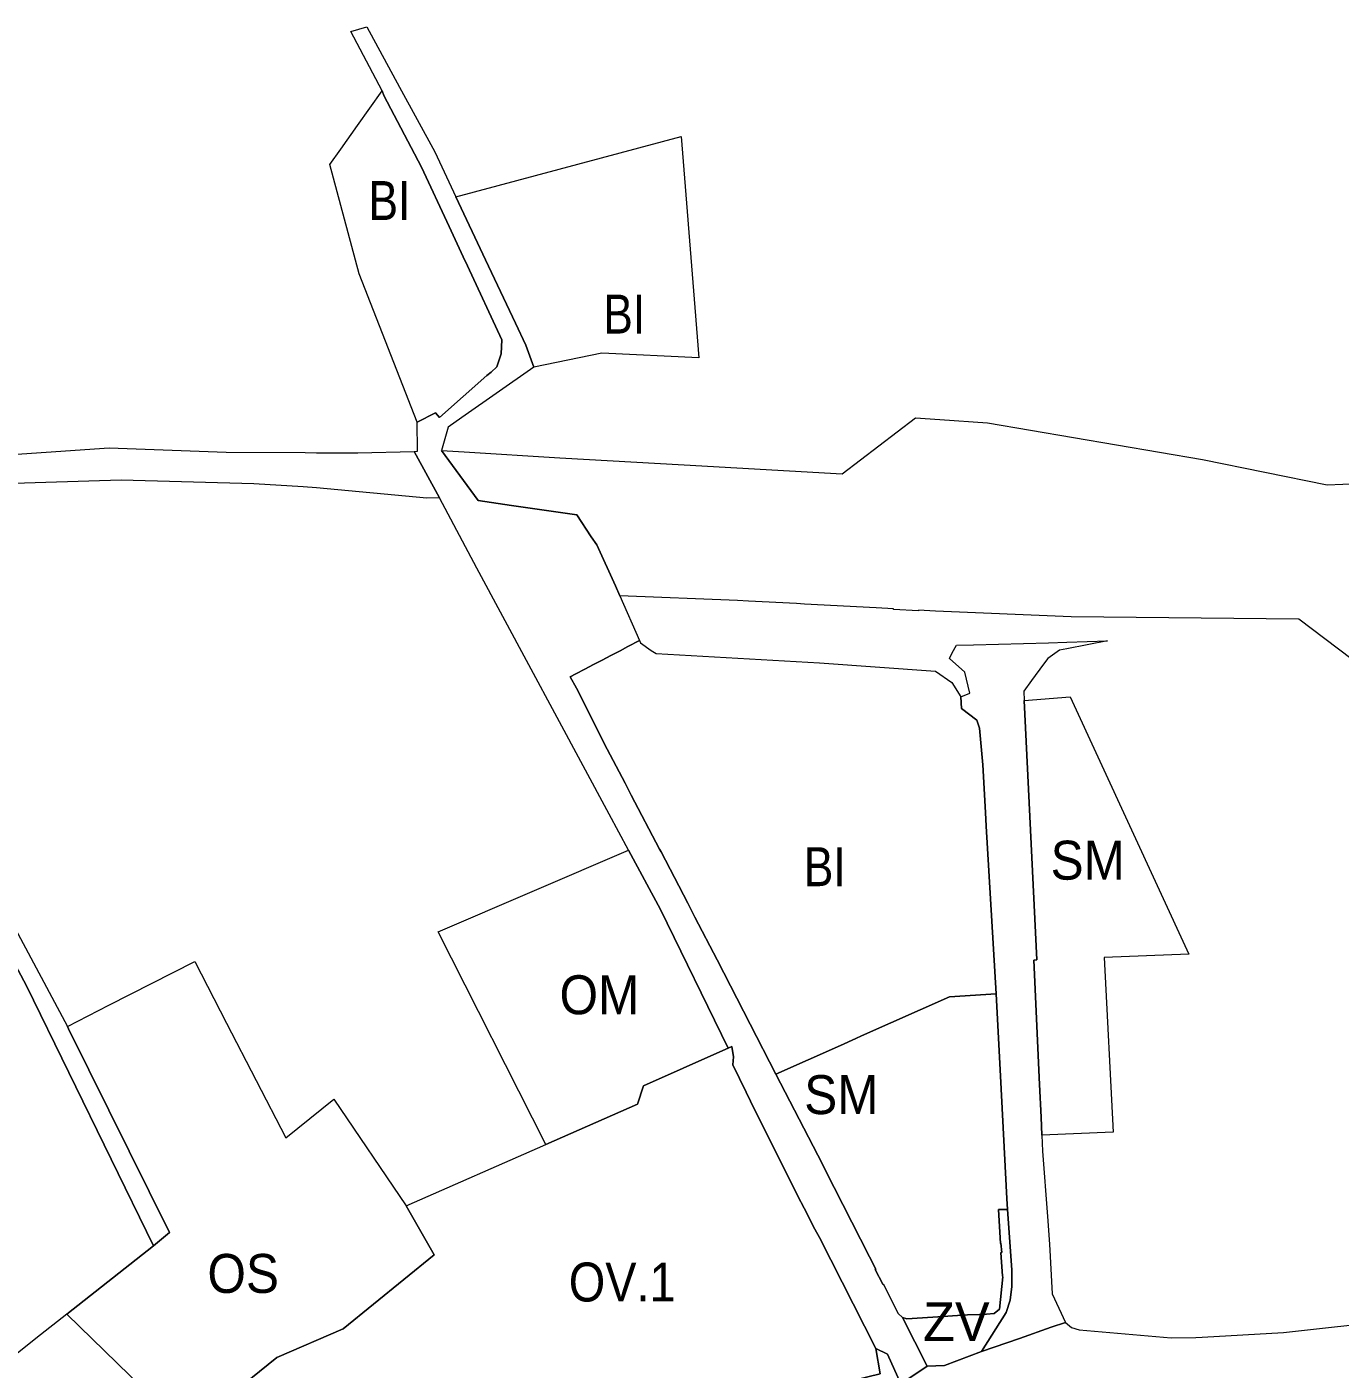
# Model space of a CAD drawing. Extents: x -650451 to -642268, y -1075216 to -1066610.
# Drawn here: x -647355.8 to -646951.4, y -1070109.3 to -1069695.9 of the extents above; entities that cross this region are included whole.
import ezdxf

# ---------------------------------------------------------------- set-up
doc = ezdxf.new("R2010")
doc.units = 0
doc.header["$LTSCALE"] = 4.8
for name, color, linetype, lineweight in [('11', 7, 'Continuous', 13), ('12', 7, 'Continuous', 13), ('15', 7, 'Continuous', 13), ('18', 7, 'Continuous', 13), ('2', 7, 'Continuous', 13), ('24', 7, 'Continuous', 13), ('25', 7, 'Continuous', 13), ('40', 7, 'Continuous', 13), ('9', 7, 'Continuous', 13)]:
    doc.layers.add(name, color=color, linetype=linetype, lineweight=lineweight)
doc.layers.add('62', color=7, linetype='Continuous')

msp = doc.modelspace()

# ---------------------------------------------------------------- linework, layer by layer
at = {"layer": '11'}
for points in [[(-647195.933, -1070040.107), (-647167.8, -1070027.73), (-647165.92, -1070022.1), (-647141.46, -1070011.19), (-647139.86, -1070010.451)], [(-647139.86, -1070010.451), (-647138.71, -1070009.92), (-647138.21, -1070013.07), (-647138.45, -1070015.59), (-647134.3, -1070023.97), (-647132.94, -1070026.73), (-647118.36, -1070056.05), (-647116.41, -1070059.73), (-647113.14, -1070066.15), (-647111.72, -1070068.77), (-647094.36, -1070102.91)], [(-647291.67, -1070116.04), (-647278.81, -1070105.73), (-647258.36, -1070096.89), (-647230.37, -1070074.09), (-647238.99, -1070059.05), (-647195.933, -1070040.107)], [(-647094.36, -1070102.91), (-647093.03, -1070110.71), (-647109.06, -1070114.67), (-647134.29, -1070122.54), (-647167.62, -1070135.33), (-647196.84, -1070150.3), (-647219.58, -1070158.11), (-647224.72, -1070159.87)]]:
    msp.add_lwpolyline(points, dxfattribs=at)
at = {"layer": '12'}
msp.add_line((-647229.096, -1069974.658), (-647170.546, -1069949.42), dxfattribs=at)
for points in [[(-647170.546, -1069949.42), (-647160.71, -1069967.74), (-647139.86, -1070010.451)], [(-647139.86, -1070010.451), (-647141.46, -1070011.19), (-647165.92, -1070022.1), (-647167.8, -1070027.73), (-647195.933, -1070040.107), (-647229.096, -1069974.658)]]:
    msp.add_lwpolyline(points, dxfattribs=at)
at = {"layer": '15'}
for points in [[(-647256.061, -1069697.32), (-647251.13, -1069695.888), (-647240.994, -1069714.513)], [(-647235.62, -1069817.62), (-647230, -1069814.75), (-647228.68, -1069816.21), (-647214.1, -1069803.32), (-647212.84, -1069802.21), (-647211.02, -1069800.57), (-647209.74, -1069796.63), (-647209.55, -1069792.27), (-647220.12, -1069769.51), (-647221.43, -1069766.68), (-647225.73, -1069757.43), (-647234.25, -1069739.09), (-647245.83, -1069716.99), (-647246.42, -1069715.63), (-647256.061, -1069697.32)], [(-647240.994, -1069714.513), (-647230.16, -1069734.42), (-647223.66, -1069748.26)], [(-647223.66, -1069748.26), (-647214.56, -1069767.62), (-647205.37, -1069787.19), (-647202.17, -1069793.89), (-647199.65, -1069800.69)], [(-647199.65, -1069800.69), (-647221.87, -1069816.21), (-647226.04, -1069819.17), (-647228.12, -1069826.33)], [(-647236.5, -1069826.63), (-647235.48, -1069826.59), (-647235.49, -1069826.51), (-647235.62, -1069817.62)], [(-647139.86, -1070010.451), (-647160.71, -1069967.74), (-647170.546, -1069949.42), (-647176.499, -1069938.333), (-647217.177, -1069862.57), (-647228.77, -1069840.98), (-647236.5, -1069826.63)], [(-647228.12, -1069826.33), (-647216.82, -1069841.82), (-647206.6, -1069843.28), (-647186.43, -1069846.14), (-647181.99, -1069852.94), (-647180.29, -1069855.47), (-647174.58, -1069868.03), (-647173.23, -1069871.09), (-647167.14, -1069884.85)], [(-647433.48, -1069851.02), (-647427.62, -1069845.94), (-647413.462, -1069872.442), (-647343.28, -1070003.81)], [(-647316.82, -1070071.35), (-647355.89, -1069991.27), (-647399.62, -1069909.23), (-647428.49, -1069859.62), (-647433.48, -1069851.02)], [(-647167.14, -1069884.85), (-647170.7, -1069886.73), (-647173.11, -1069888.06), (-647175.97, -1069889.5), (-647178.65, -1069890.92), (-647181.28, -1069892.3), (-647183.94, -1069893.7), (-647186.76, -1069895.19), (-647188.44, -1069896.08), (-647186.59, -1069899.62), (-647177.05, -1069918.33), (-647171.55, -1069928.83), (-647169.72, -1069932.48), (-647160.94, -1069949.14), (-647160.47, -1069950.02), (-647152.31, -1069965.78), (-647150.08, -1069970.1), (-647143.26, -1069983.28), (-647133.1, -1070003.01), (-647125.2, -1070018.46)], [(-647068.2, -1069902.28), (-647065.47, -1069901.09), (-647067.02, -1069894.68), (-647071.73, -1069890.39), (-647070.87, -1069888.71), (-647069.57, -1069886.35), (-647064.32, -1069886.23), (-647041.25, -1069885.62), (-647035.6, -1069885.43), (-647023.04, -1069885), (-647035.53, -1069887.44), (-647037.79, -1069887.88), (-647041.47, -1069890.42), (-647042.75, -1069892.14), (-647046.49, -1069897.19), (-647048.8, -1069900.51), (-647048.67, -1069903.32)], [(-647057.31, -1069993.74), (-647060.38, -1069942.06), (-647060.59, -1069937.88), (-647061.39, -1069923.19), (-647062.44, -1069911.94), (-647063.25, -1069909.42), (-647067.96, -1069905.87), (-647068.2, -1069902.28)], [(-647048.67, -1069903.32), (-647044.8, -1069983.26), (-647045.73, -1069983.3), (-647043.97, -1070021.61), (-647043.51, -1070031.7), (-647043.25, -1070037.29)], [(-647053.86, -1070060.1), (-647054.03, -1070056.73), (-647055.98, -1070019.12), (-647057.31, -1069993.74)], [(-647343.28, -1070003.81), (-647342.93, -1070004.49), (-647311.89, -1070067.23), (-647316.82, -1070071.35)], [(-647094.36, -1070102.91), (-647111.72, -1070068.77), (-647113.14, -1070066.15), (-647116.41, -1070059.73), (-647118.36, -1070056.05), (-647132.94, -1070026.73), (-647134.3, -1070023.97), (-647138.45, -1070015.59), (-647138.21, -1070013.07), (-647138.71, -1070009.92), (-647139.86, -1070010.451)], [(-647125.2, -1070018.46), (-647112.23, -1070043.4), (-647107.18, -1070053.37), (-647104.54, -1070058.59), (-647096.36, -1070074.72), (-647094.37, -1070078.48), (-647094.54, -1070078.57), (-647092.23, -1070083.18), (-647091.97, -1070083.33), (-647087.98, -1070091.17), (-647087.47, -1070092.21), (-647086.22, -1070093.37), (-647078.59, -1070108.38)], [(-647043.25, -1070037.29), (-647043.03, -1070042.14), (-647041.53, -1070062.28), (-647040.92, -1070070.85), (-647040.12, -1070086.11), (-647036.03, -1070094.96)], [(-647061.81, -1070103.88), (-647054.25, -1070091.85), (-647053.03, -1070088.07), (-647052.49, -1070083.81), (-647052.47, -1070078.72), (-647053.86, -1070060.1)], [(-647036.03, -1070094.96), (-647040.44, -1070096.38), (-647050.12, -1070099.88), (-647061.81, -1070103.88)], [(-647078.59, -1070108.38), (-647086.73, -1070113.82), (-647090.78, -1070104.66), (-647094.36, -1070102.91)]]:
    msp.add_lwpolyline(points, dxfattribs=at)
at = {"layer": '18'}
msp.add_line((-647048.67, -1069903.32), (-647034.51, -1069902.21), dxfattribs=at)
for points in [[(-647034.51, -1069902.21), (-646998.06, -1069981.49), (-647024.05, -1069982.48), (-647021.27, -1070036.28), (-647043.25, -1070037.29)], [(-647043.25, -1070037.29), (-647043.51, -1070031.7), (-647043.97, -1070021.61), (-647045.73, -1069983.3), (-647044.8, -1069983.26), (-647048.67, -1069903.32)], [(-647125.2, -1070018.46), (-647105.31, -1070009.62), (-647100.5, -1070007.48), (-647098.78, -1070006.65), (-647071.69, -1069994.67), (-647057.31, -1069993.74)], [(-647057.31, -1069993.74), (-647055.98, -1070019.12), (-647054.03, -1070056.73), (-647053.86, -1070060.1)], [(-647086.22, -1070093.37), (-647087.47, -1070092.21), (-647087.98, -1070091.17), (-647091.97, -1070083.33), (-647092.23, -1070083.18), (-647094.54, -1070078.57), (-647094.37, -1070078.48), (-647096.36, -1070074.72), (-647104.54, -1070058.59), (-647107.18, -1070053.37), (-647112.23, -1070043.4), (-647125.2, -1070018.46)], [(-647053.86, -1070060.1), (-647056.61, -1070060.11), (-647056.05, -1070070.56), (-647055.85, -1070070.55), (-647055.64, -1070073.36), (-647055.94, -1070073.38), (-647055.38, -1070080.69), (-647055.23, -1070080.85), (-647056.29, -1070090.81), (-647057.92, -1070092.22), (-647060.35, -1070092.37), (-647062.44, -1070092.46), (-647066.15, -1070092.63), (-647076.8, -1070093.25), (-647084.84, -1070093.82), (-647086.22, -1070093.37)]]:
    msp.add_lwpolyline(points, dxfattribs=at)
at = {"layer": '2'}
for points in [[(-647235.62, -1069817.62), (-647253.45, -1069771.95), (-647262.46, -1069738.25), (-647259.11, -1069733.52), (-647253.97, -1069726.27), (-647246.42, -1069715.63)], [(-647246.42, -1069715.63), (-647245.83, -1069716.99), (-647234.25, -1069739.09), (-647225.73, -1069757.43), (-647221.43, -1069766.68), (-647220.12, -1069769.51), (-647209.55, -1069792.27), (-647209.74, -1069796.63), (-647211.02, -1069800.57), (-647212.84, -1069802.21), (-647214.1, -1069803.32), (-647228.68, -1069816.21), (-647230, -1069814.75), (-647235.62, -1069817.62)], [(-647223.66, -1069748.26), (-647154.33, -1069729.69), (-647150.138, -1069782.334), (-647148.9, -1069797.88)], [(-647199.65, -1069800.69), (-647202.17, -1069793.89), (-647205.37, -1069787.19), (-647214.56, -1069767.62), (-647223.66, -1069748.26)], [(-647148.9, -1069797.88), (-647178.73, -1069796.4), (-647199.65, -1069800.69)], [(-647125.2, -1070018.46), (-647133.1, -1070003.01), (-647143.26, -1069983.28), (-647150.08, -1069970.1), (-647152.31, -1069965.78), (-647160.47, -1069950.02), (-647160.94, -1069949.14), (-647169.72, -1069932.48), (-647171.55, -1069928.83), (-647177.05, -1069918.33), (-647186.59, -1069899.62), (-647188.44, -1069896.08), (-647186.76, -1069895.19), (-647183.94, -1069893.7), (-647181.28, -1069892.3), (-647178.65, -1069890.92), (-647175.97, -1069889.5), (-647173.11, -1069888.06), (-647170.7, -1069886.73), (-647167.14, -1069884.85)], [(-647167.14, -1069884.85), (-647166.8, -1069885.63), (-647163.55, -1069887.98), (-647162.03, -1069888.89), (-647111.76, -1069891.77), (-647075.97, -1069894.33), (-647071, -1069897.87), (-647068.2, -1069902.28)], [(-647068.2, -1069902.28), (-647067.96, -1069905.87), (-647063.25, -1069909.42), (-647062.44, -1069911.94), (-647061.39, -1069923.19), (-647060.59, -1069937.88), (-647060.38, -1069942.06), (-647057.31, -1069993.74)], [(-647057.31, -1069993.74), (-647071.69, -1069994.67), (-647098.78, -1070006.65), (-647100.5, -1070007.48), (-647105.31, -1070009.62), (-647125.2, -1070018.46)]]:
    msp.add_lwpolyline(points, dxfattribs=at)
at = {"layer": '24'}
for points in [[(-647036.03, -1070094.96), (-647034.17, -1070096.49), (-647031.73, -1070097.21), (-647003.49, -1070099.66), (-646995.86, -1070099.52), (-646993.92, -1070099.49), (-646968.89, -1070098.02), (-646934.63, -1070094.24), (-646925.08, -1070093.82), (-646918.75, -1070094.08), (-646904.97, -1070094.52), (-646874.9, -1070094.1), (-646859.29, -1070093.1), (-646821.89, -1070090.7), (-646817.15, -1070084.76)], [(-647061.81, -1070103.88), (-647050.12, -1070099.88), (-647040.44, -1070096.38), (-647036.03, -1070094.96)], [(-647224.72, -1070159.87), (-647219.58, -1070158.11), (-647196.84, -1070150.3), (-647167.62, -1070135.33), (-647134.29, -1070122.54), (-647109.06, -1070114.67), (-647093.03, -1070110.71), (-647094.36, -1070102.91)], [(-647094.36, -1070102.91), (-647090.78, -1070104.66), (-647086.73, -1070113.82), (-647078.59, -1070108.38)], [(-647078.59, -1070108.38), (-647073.28, -1070108.15), (-647061.81, -1070103.88)]]:
    msp.add_lwpolyline(points, dxfattribs=at)
at = {"layer": '25'}
for points in [[(-647228.12, -1069826.33), (-647221.14, -1069826.761), (-647191.66, -1069828.58), (-647153.36, -1069830.79), (-647104.741, -1069833.568), (-647082.145, -1069816.321)], [(-647082.145, -1069816.321), (-647074.72, -1069816.8), (-647060.029, -1069817.854)], [(-647060.029, -1069817.854), (-646993.81, -1069829.12), (-646955.45, -1069836.93), (-646940.94, -1069836.34)], [(-647428.993, -1069836.714), (-647369.3, -1069828.22), (-647330.46, -1069825.51), (-647294.38, -1069826.88), (-647270.09, -1069827.02), (-647266.581, -1069827.042), (-647256.034, -1069827.107)], [(-647256.034, -1069827.107), (-647253.88, -1069827.12), (-647236.5, -1069826.63), (-647228.77, -1069840.98)], [(-647173.23, -1069871.09), (-647174.58, -1069868.03), (-647180.29, -1069855.47), (-647181.99, -1069852.94), (-647186.43, -1069846.14), (-647206.6, -1069843.28), (-647216.82, -1069841.82), (-647228.12, -1069826.33)], [(-647228.77, -1069840.98), (-647232.66, -1069841.07), (-647266.62, -1069837.86), (-647270.71, -1069837.61), (-647285.9, -1069836.66), (-647326.71, -1069835.46), (-647363.21, -1069836.64), (-647425.73, -1069844.31), (-647427.62, -1069845.94), (-647433.48, -1069851.02)], [(-646931.67, -1069902.89), (-646964.111, -1069878.315), (-647034.195, -1069877.629), (-647076, -1069875.85), (-647081.25, -1069875.56), (-647081.26, -1069875.76), (-647088.94, -1069875.34), (-647088.93, -1069875.14), (-647094.24, -1069874.85), (-647116.31, -1069873.65), (-647118.77, -1069873.51), (-647133.58, -1069872.73), (-647136.94, -1069872.55), (-647173.23, -1069871.09)]]:
    msp.add_lwpolyline(points, dxfattribs=at)
at = {"layer": '40'}
for points in [[(-647433.48, -1069851.02), (-647428.49, -1069859.62), (-647399.62, -1069909.23), (-647355.89, -1069991.27), (-647316.82, -1070071.35), (-647343.454, -1070092.368)], [(-647086.22, -1070093.37), (-647084.84, -1070093.82), (-647076.8, -1070093.25), (-647066.15, -1070092.63), (-647062.44, -1070092.46), (-647060.35, -1070092.37), (-647057.92, -1070092.22), (-647056.29, -1070090.81), (-647055.23, -1070080.85), (-647055.38, -1070080.69), (-647055.94, -1070073.38), (-647055.64, -1070073.36), (-647055.85, -1070070.55), (-647056.05, -1070070.56), (-647056.61, -1070060.11), (-647053.86, -1070060.1)], [(-647053.86, -1070060.1), (-647052.47, -1070078.72), (-647052.49, -1070083.81), (-647053.03, -1070088.07), (-647054.25, -1070091.85), (-647061.81, -1070103.88)], [(-647343.454, -1070092.368), (-647352.96, -1070099.87), (-647362.87, -1070107.74), (-647371.716, -1070098.46)], [(-647061.81, -1070103.88), (-647073.28, -1070108.15), (-647078.59, -1070108.38), (-647086.22, -1070093.37)]]:
    msp.add_lwpolyline(points, dxfattribs=at)
at = {"layer": '9'}
msp.add_line((-647343.454, -1070092.368), (-647316.82, -1070071.35), dxfattribs=at)
for points in [[(-647343.28, -1070003.81), (-647330.5, -1069997.19), (-647304.05, -1069983.79), (-647294.257, -1070002.745)], [(-647316.82, -1070071.35), (-647311.89, -1070067.23), (-647342.93, -1070004.49), (-647343.28, -1070003.81)], [(-647294.257, -1070002.745), (-647276, -1070038.08), (-647261.27, -1070026.12), (-647238.99, -1070059.05)], [(-647238.99, -1070059.05), (-647230.37, -1070074.09), (-647258.36, -1070096.89), (-647278.81, -1070105.73), (-647291.67, -1070116.04)], [(-647291.67, -1070116.04), (-647295.47, -1070119.09), (-647298.91, -1070114.8), (-647312.485, -1070122.583), (-647343.454, -1070092.368)]]:
    msp.add_lwpolyline(points, dxfattribs=at)

# ---------------------------------------------------------------- texts
at = {"layer": '62'}
for s, width, p in [('BI', 0.85, (-647250.575, -1069755.387)), ('BI', 0.85, (-647178.277, -1069790.357)), ('SM', 0.95, (-647040.574, -1069958.547)), ('BI', 0.85, (-647116.546, -1069960.56)), ('OM', 0.95, (-647191.763, -1070000.002)), ('SM', 0.95, (-647116.431, -1070030.76)), ('OS', 0.95, (-647300.17, -1070085.831)), ('OV.1', 0.9, (-647188.922, -1070088.468))]:
    msp.add_text(s, height=12, dxfattribs=dict(at, width=width)).set_placement(p)
msp.add_text('ZV', height=12, dxfattribs=at).set_placement((-647079.826, -1070100.687))

doc.saveas('drawing.dxf')
